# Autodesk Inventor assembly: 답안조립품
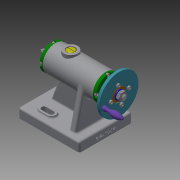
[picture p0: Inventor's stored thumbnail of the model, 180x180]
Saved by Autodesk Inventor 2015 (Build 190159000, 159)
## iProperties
Created: 2022-06
Part Number: 답안조립품
Document SubType Name: Assembly
Designer: 10415
Author: 10415
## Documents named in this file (18)
- C:\Users\10415\Desktop\720606V1009\답안조립품.iam
- C:\Users\10415\Desktop\720606V1009\나사.ipt
- C:\Users\10415\Desktop\720606V1009\나사축.ipt
- C:\Users\10415\Desktop\720606V1009\너트 M8.ipt
- C:\Users\10415\Desktop\720606V1009\돌림판.ipt
- C:\Users\10415\Desktop\720606V1009\멈춤나사 M3.ipt
- C:\Users\10415\Desktop\720606V1009\본체.ipt
- C:\Users\10415\Desktop\720606V1009\볼트 M3.ipt
- C:\Users\10415\Desktop\720606V1009\부시.ipt
- C:\Users\10415\Desktop\720606V1009\센터.ipt
- C:\Users\10415\Desktop\720606V1009\센터홀더.ipt
- C:\Users\10415\Desktop\720606V1009\슬리브.ipt
- C:\Users\10415\Desktop\720606V1009\와셔.ipt
- C:\Users\10415\Desktop\720606V1009\중공축.ipt
- C:\Users\10415\Desktop\720606V1009\커버.ipt
- C:\Users\10415\Desktop\720606V1009\키 4 x 4 x 10.ipt
- C:\Users\10415\Desktop\720606V1009\플랜지.ipt
- C:\Users\10415\Desktop\720606V1009\핸들.ipt
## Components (2 placed, 2 different names)
1. 플랜지:1 — 각도:2
2. 핸들:1
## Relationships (1: Angle 1)
- 각도:2 [Angle]: 플랜지:1
